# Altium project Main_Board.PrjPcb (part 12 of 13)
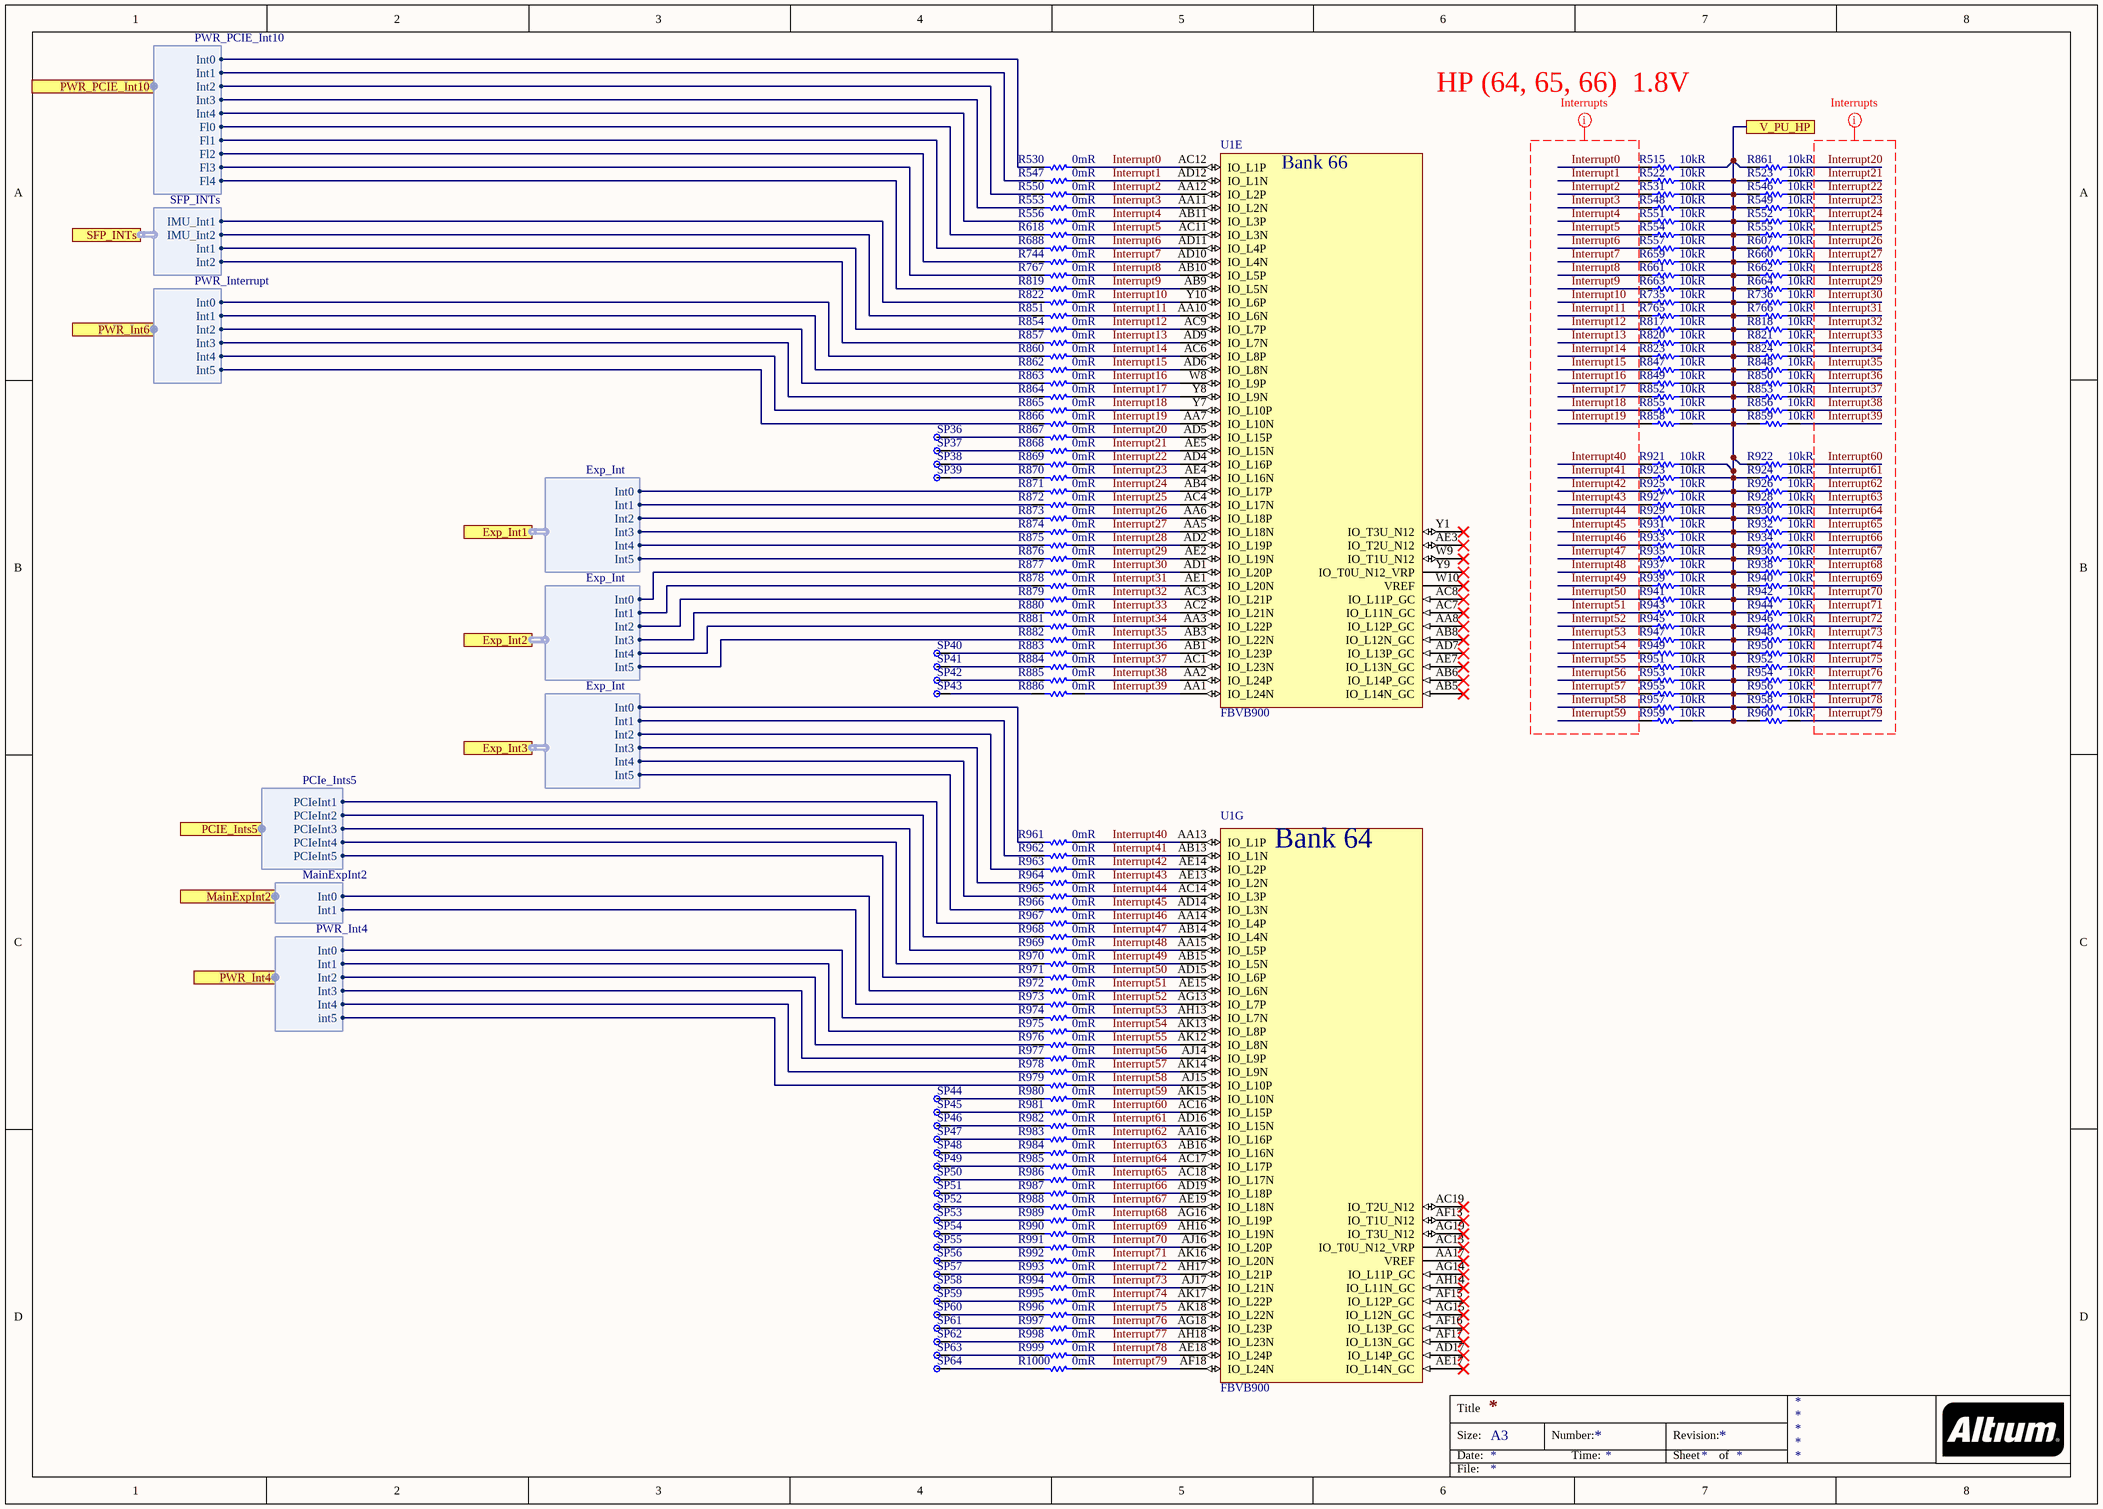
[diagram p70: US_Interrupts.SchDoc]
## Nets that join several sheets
B503_Ground: Ultrascale+_01 (13 pins), PS_Config (25 pins), LED_US_1 (9 pins), WR_Clock (5 pins), Ultrascale+_02 (U15.2 U15.10), JESD204_B_or_C (R450.2 R452.2 R454.2), HighSpeed/PCIE0 (23 pins), HighSpeed/PCIE1 (23 pins), HighSpeed/PCIE2 (23 pins), HighSpeed/PCIE3 (23 pins), HighSpeed/PCIE4 (23 pins), HighSpeed/I2C_Bridge_PCIE (C303_I2C_Bridge_PCIE.1 U3_I2C_Bridge_PCIE.9 U3_I2C_Bridge_PCIE.25), HighSpeed/SPI_bridge_PCIe (10 pins), Power4HiSpeed (50 pins), HighSpeed/Power4HighSpeed/U_Pomiar_pradu_napiecia_PCIe0 (C309_U_Pomiar_pradu_napiecia_PCIe0.1 U64_U_Pomiar_pradu_napiecia_PCIe0.7), HighSpeed/Power4HighSpeed/U_Pomiar_pradu_napiecia_PCIe1 (C309_U_Pomiar_pradu_napiecia_PCIe1.1 U64_U_Pomiar_pradu_napiecia_PCIe1.7), HighSpeed/Power4HighSpeed/U_Pomiar_pradu_napiecia_PCIe2 (C309_U_Pomiar_pradu_napiecia_PCIe2.1 U64_U_Pomiar_pradu_napiecia_PCIe2.7), HighSpeed/Power4HighSpeed/U_Pomiar_pradu_napiecia_PCIe3 (C309_U_Pomiar_pradu_napiecia_PCIe3.1 U64_U_Pomiar_pradu_napiecia_PCIe3.7), HighSpeed/Power4HighSpeed/U_Pomiar_pradu_napiecia_PCIe4 (C309_U_Pomiar_pradu_napiecia_PCIe4.1 U64_U_Pomiar_pradu_napiecia_PCIe4.7), Power_Distribution (13 pins), Power_Switch (85 pins), Power_Hi_Curr (21 pins), HI_Curr_ADP1850 (53 pins), Power_ADP1850_Dual (47 pins), Power_ADP1850_Dual_1 (47 pins), PowerDistribition/HiCurrent/U_Pomiar_pradu_napiecia_3 (C309_U_Pomiar_pradu_napiecia_3.1 U64_U_Pomiar_pradu_napiecia_3.7), PowerDistribition/HiCurrent/U_Pomiar_pradu_napiecia_4 (C309_U_Pomiar_pradu_napiecia_4.1 U64_U_Pomiar_pradu_napiecia_4.7), PowerDistribition/HiCurrent/U_Pomiar_pradu_napiecia_5 (C309_U_Pomiar_pradu_napiecia_5.1 U64_U_Pomiar_pradu_napiecia_5.7), PowerDistribition/HiCurrent/U_Pomiar_pradu_napiecia_6 (C309_U_Pomiar_pradu_napiecia_6.1 U64_U_Pomiar_pradu_napiecia_6.7), Pomiar_napiecia_high_curr (C310.1 U72.7), Power_Low_Curr (34 pins), Zasilanie_CLKDistribution (5 pins), PowerDistribition/Zasilanie CLK/I2C_Expander_PWR_CLK (C311_I2C_Expander_PWR_CLK.1 U35_I2C_Expander_PWR_CLK.6 U35_I2C_Expander_PWR_CLK.29), RAM_Power (136 pins), XilinxPower (10 pins), FPGA_Decoupling (28 pins), RAM (7 pins), Ground (286 pins), Power_Ethernet (20 pins), PowerDistribition/I2C_Expander_PWR_Dist (C311_I2C_Expander_PWR_Dist.1 U35_I2C_Expander_PWR_Dist.6 U35_I2C_Expander_PWR_Dist.29), PowerDistribition/U_Pomiar_pradu_napiecia_1 (C309_U_Pomiar_pradu_napiecia_1.1 U64_U_Pomiar_pradu_napiecia_1.7), PowerDistribition/U_Pomiar_pradu_napiecia_2 (C309_U_Pomiar_pradu_napiecia_2.1 U64_U_Pomiar_pradu_napiecia_2.7), Power_48_20V@3A (R764.1), TPS7A88_3V3_1V8_0V9V@2x1A (13 pins), ADP1741_3V3_0V85 (8 pins), ST1L08_5V_0V6 (7 pins), Power_LED (20 pins), Trans_LS_I2C0 (U36_Trans_LS_I2C0.1), GPIO_I2C (R242.2 R244.2 R400.2), Ext_GPIO/I2C_Bridge_GPIO (C303_I2C_Bridge_GPIO.1 U3_I2C_Bridge_GPIO.9 U3_I2C_Bridge_GPIO.25), Ext_GPIO_Bank0 (9 pins), Ext_GPIO/Ext_GPIO_Bank0/I2C_Expander_00 (C311_I2C_Expander_00.1 U35_I2C_Expander_00.6 U35_I2C_Expander_00.29), Ext_GPIO/Ext_GPIO_Bank0/I2C_Expander_01 (C311_I2C_Expander_01.1 U35_I2C_Expander_01.6 U35_I2C_Expander_01.29), Ext_GPIO/Ext_GPIO_Bank0/I2C_Expander_02 (C311_I2C_Expander_02.1 U35_I2C_Expander_02.6 U35_I2C_Expander_02.29), Ext_GPIO_Bank1 (9 pins), Ext_GPIO/Ext_GPIO_Bank1/I2C_Expander_10 (C311_I2C_Expander_10.1 U35_I2C_Expander_10.6 U35_I2C_Expander_10.29), Ext_GPIO/Ext_GPIO_Bank1/I2C_Expander_11 (C311_I2C_Expander_11.1 U35_I2C_Expander_11.6 U35_I2C_Expander_11.29), Ext_GPIO/Ext_GPIO_Bank1/I2C_Expander_12 (C311_I2C_Expander_12.1 U35_I2C_Expander_12.6 U35_I2C_Expander_12.29), SFP_Group (6 pins), SFP (12 pins), SFP1 (12 pins), SFP2 (12 pins), SFP3 (12 pins), SFP_Group+IMU/I2C_Bridge_SFP (C303_I2C_Bridge_SFP.1 U3_I2C_Bridge_SFP.9 U3_I2C_Bridge_SFP.25), IMU (7 pins), SFP_Group+IMU/I2C_Expander_SFP (C311_I2C_Expander_SFP.1 U35_I2C_Expander_SFP.6 U35_I2C_Expander_SFP.29), Trans_PS_I2C0 (U36_Trans_PS_I2C0.1), Trans_PS_I2C1 (U36_Trans_PS_I2C1.1), SPI_bridge_Main (10 pins), Trans_LS_I2C1 (U36_Trans_LS_I2C1.1), Detektor_otwarcia (12 pins), RJ45 (49 pins), Sata (16 pins), uSD (7 pins), FTDI (11 pins), USB3 (30 pins), CAN (C585.1 U63.2 U63.8 U75.3), eMMC (30 pins), Expander_RESET (5 pins), U_Expander_RESET/I2C_Expander_Main_Rst (C311_I2C_Expander_Main_Rst.1 U35_I2C_Expander_Main_Rst.6 U35_I2C_Expander_Main_Rst.29)
0.85V@40A_INA: HI_Curr_ADP1850 (26 pins), Pomiar_napiecia_high_curr (R617.1 U72.10)
0V9@1A_REG3: XilinxPower (6 pins), TPS7A88_3V3_1V8_0V9V@2x1A (5 pins)
0V85@2A: XilinxPower (U1.J23 U1.L23), FPGA_Decoupling (C746.2), ADP1741_3V3_0V85 (C675.2 FB45.2)
1V0@1.5A: Power_Ethernet (C555.2 R397.2 U51.8), RJ45 (14 pins)
1V8@0.5A_ADC_filtered: XilinxPower (14 pins), FPGA_Decoupling (C749.2 C750.2 C757.1 C758.2), TPS7A88_3V3_1V8_0V9V@2x1A (6 pins)
1V8@1.5A: Power_Ethernet (C553.2 R394.2 U50.8), IMU (C561.2 U58.8), RJ45 (8 pins), USB3 (C1.2 C2.2 U45.28 U45.30)
2V5@1.5A: RAM_Power (16 pins), Power_Ethernet (C551.2 R391.2 R392.2 U49.8), RJ45 (8 pins)
3.3V_LN_1: Zasilanie_CLKDistribution (12 pins), ADP1741_3.6V_3.3V@2A (C569.2 FB33.2)
3.3V_Stable_1: Zasilanie_CLKDistribution (38 pins), PowerDistribition/Zasilanie CLK/5to3V3_1 (6 pins)
3.3V_Stable_2: Zasilanie_CLKDistribution (38 pins), PowerDistribition/Zasilanie CLK/5to3V3_2 (6 pins)
3V3_NVMe: Power_Hi_Curr (8 pins), Sata (9 pins)
3V3_RAIL: LED_US_1 (9 pins), CLK_Mux (6 pins), Ultrascale+_02 (R124.2 U15.15), JESD204_B_or_C (R449.1 R451.1 R453.1), HighSpeed/PCIE0 (F1_PCIE0.2), HighSpeed/PCIE1 (F1_PCIE1.2), HighSpeed/PCIE2 (F1_PCIE2.2), HighSpeed/PCIE3 (F1_PCIE3.2), HighSpeed/PCIE4 (F1_PCIE4.2), HighSpeed/I2C_Bridge_PCIE (19 pins), HighSpeed/SPI_bridge_PCIe (30 pins), Power4HiSpeed (10 pins), HighSpeed/Power4HighSpeed/U_Pomiar_pradu_napiecia_PCIe0 (C309_U_Pomiar_pradu_napiecia_PCIe0.2 U64_U_Pomiar_pradu_napiecia_PCIe0.6), HighSpeed/Power4HighSpeed/U_Pomiar_pradu_napiecia_PCIe1 (C309_U_Pomiar_pradu_napiecia_PCIe1.2 U64_U_Pomiar_pradu_napiecia_PCIe1.6), HighSpeed/Power4HighSpeed/U_Pomiar_pradu_napiecia_PCIe2 (C309_U_Pomiar_pradu_napiecia_PCIe2.2 U64_U_Pomiar_pradu_napiecia_PCIe2.6), HighSpeed/Power4HighSpeed/U_Pomiar_pradu_napiecia_PCIe3 (C309_U_Pomiar_pradu_napiecia_PCIe3.2 U64_U_Pomiar_pradu_napiecia_PCIe3.6), HighSpeed/Power4HighSpeed/U_Pomiar_pradu_napiecia_PCIe4 (C309_U_Pomiar_pradu_napiecia_PCIe4.2 U64_U_Pomiar_pradu_napiecia_PCIe4.6), Power_Distribution (7 pins), Power_Switch (5 pins), Power_Hi_Curr (18 pins), Power_ADP1850_Dual (R287.2), PowerDistribition/HiCurrent/U_Pomiar_pradu_napiecia_3 (5 pins), PowerDistribition/HiCurrent/U_Pomiar_pradu_napiecia_4 (C309_U_Pomiar_pradu_napiecia_4.2 U64_U_Pomiar_pradu_napiecia_4.6), PowerDistribition/HiCurrent/U_Pomiar_pradu_napiecia_5 (C309_U_Pomiar_pradu_napiecia_5.2 U64_U_Pomiar_pradu_napiecia_5.6), PowerDistribition/HiCurrent/U_Pomiar_pradu_napiecia_6 (C309_U_Pomiar_pradu_napiecia_6.2 U64_U_Pomiar_pradu_napiecia_6.6), Pomiar_napiecia_high_curr (C310.2 U72.6), Power_Low_Curr (C623.2 U19.13 U19.16 U67.1), Zasilanie_CLKDistribution (R738.1 R740.1 R742.1), PowerDistribition/Zasilanie CLK/I2C_Expander_PWR_CLK (C311_I2C_Expander_PWR_CLK.2 U35_I2C_Expander_PWR_CLK.5), Power_Ethernet (14 pins), PowerDistribition/I2C_Expander_PWR_Dist (C311_I2C_Expander_PWR_Dist.2 U35_I2C_Expander_PWR_Dist.5), PowerDistribition/U_Pomiar_pradu_napiecia_1 (C309_U_Pomiar_pradu_napiecia_1.2 U64_U_Pomiar_pradu_napiecia_1.6), PowerDistribition/U_Pomiar_pradu_napiecia_2 (C309_U_Pomiar_pradu_napiecia_2.2 U64_U_Pomiar_pradu_napiecia_2.6), TPS7A88_3V3_1V8_0V9V@2x1A (7 pins), ADP1741_3V3_0V85 (7 pins), ST1L08_5V_0V6 (C721.2 R691.1 U73.2), Power_LED (18 pins), Trans_LS_I2C0 (R1122_Trans_LS_I2C0.1), GPIO_I2C (9 pins), Ext_GPIO/I2C_Bridge_GPIO (19 pins), Ext_GPIO_Bank0 (9 pins), Ext_GPIO/Ext_GPIO_Bank0/I2C_Expander_00 (C311_I2C_Expander_00.2 U35_I2C_Expander_00.5), Ext_GPIO/Ext_GPIO_Bank0/I2C_Expander_01 (C311_I2C_Expander_01.2 U35_I2C_Expander_01.5), Ext_GPIO/Ext_GPIO_Bank0/I2C_Expander_02 (C311_I2C_Expander_02.2 U35_I2C_Expander_02.5), Ext_GPIO_Bank1 (9 pins), Ext_GPIO/Ext_GPIO_Bank1/I2C_Expander_10 (C311_I2C_Expander_10.2 U35_I2C_Expander_10.5), Ext_GPIO/Ext_GPIO_Bank1/I2C_Expander_11 (C311_I2C_Expander_11.2 U35_I2C_Expander_11.5), Ext_GPIO/Ext_GPIO_Bank1/I2C_Expander_12 (C311_I2C_Expander_12.2 U35_I2C_Expander_12.5), SFP_Group (6 pins), SFP (8 pins), SFP1 (8 pins), SFP2 (8 pins), SFP3 (8 pins), SFP_Group+IMU/I2C_Bridge_SFP (19 pins), IMU (C562.2 R429.2 R600.2 U58.5), SFP_Group+IMU/I2C_Expander_SFP (C311_I2C_Expander_SFP.2 U35_I2C_Expander_SFP.5), Trans_PS_I2C0 (R1122_Trans_PS_I2C0.1 U36_Trans_PS_I2C0.2), Trans_PS_I2C1 (R1122_Trans_PS_I2C1.1), SPI_bridge_Main (30 pins), Trans_LS_I2C1 (R1122_Trans_LS_I2C1.1), uSD (C545.2 C546.2 J28.4 U47.A4), FTDI (8 pins), USB3 (7 pins), CAN (C585.2 U63.3), Expander_RESET (16 pins), U_Expander_RESET/I2C_Expander_Main_Rst (C311_I2C_Expander_Main_Rst.2 U35_I2C_Expander_Main_Rst.5)
5V_LN: DAC (R608.1 U30.1 U30.5 X2.14), Zasilanie_CLKDistribution (U12.42), LT3042_12V_5V_LNLDO (5 pins)
5V_RAIL: Power_ADP1850_Dual_1 (R315.2), PowerDistribition/HiCurrent/U_Pomiar_pradu_napiecia_6 (R448_U_Pomiar_pradu_napiecia_6.2 U64_U_Pomiar_pradu_napiecia_6.8 U64_U_Pomiar_pradu_napiecia_6.9), PowerDistribition/Zasilanie CLK/5to3V3_1 (C563_5to3V3_1.2 C564_5to3V3_1.2 U59_5to3V3_1.1 U59_5to3V3_1.2), PowerDistribition/Zasilanie CLK/5to3V3_2 (C563_5to3V3_2.2 C564_5to3V3_2.2 U59_5to3V3_2.1 U59_5to3V3_2.2), TPS7A88_5V_Dual_3.3V_3.3V (6 pins), ST1L08_5V_0V6 (C720.2 U73.1), Detektor_otwarcia (6 pins), USB3 (10 pins), eMMC (8 pins)
12V_LT3042: Power4HiSpeed (35 pins), Power_ADP1850_Dual_1 (R626.2), PowerDistribition/HiCurrent/U_Pomiar_pradu_napiecia_5 (R448_U_Pomiar_pradu_napiecia_5.2 U64_U_Pomiar_pradu_napiecia_5.8 U64_U_Pomiar_pradu_napiecia_5.9), Power_Low_Curr (10 pins), LT3042_12V_5V_LNLDO (FB34.1), UM78M_12_8V (C714.2 U71.1)
12V_PCIE0: Power4HiSpeed (7 pins), HighSpeed/Power4HighSpeed/U_Pomiar_pradu_napiecia_PCIe0 (R448_U_Pomiar_pradu_napiecia_PCIe0.1 U64_U_Pomiar_pradu_napiecia_PCIe0.10)
12V_PCIE0_CM: HighSpeed/PCIE0 (J1_PCIE0.2 J1_PCIE0.4), HighSpeed/Power4HighSpeed/U_Pomiar_pradu_napiecia_PCIe0 (R448_U_Pomiar_pradu_napiecia_PCIe0.2 U64_U_Pomiar_pradu_napiecia_PCIe0.8 U64_U_Pomiar_pradu_napiecia_PCIe0.9)
12V_PCIE1: Power4HiSpeed (7 pins), HighSpeed/Power4HighSpeed/U_Pomiar_pradu_napiecia_PCIe1 (R448_U_Pomiar_pradu_napiecia_PCIe1.1 U64_U_Pomiar_pradu_napiecia_PCIe1.10)
12V_PCIE1_CM: HighSpeed/PCIE1 (J1_PCIE1.2 J1_PCIE1.4), HighSpeed/Power4HighSpeed/U_Pomiar_pradu_napiecia_PCIe1 (R448_U_Pomiar_pradu_napiecia_PCIe1.2 U64_U_Pomiar_pradu_napiecia_PCIe1.8 U64_U_Pomiar_pradu_napiecia_PCIe1.9)
12V_PCIE2: Power4HiSpeed (7 pins), HighSpeed/Power4HighSpeed/U_Pomiar_pradu_napiecia_PCIe2 (R448_U_Pomiar_pradu_napiecia_PCIe2.1 U64_U_Pomiar_pradu_napiecia_PCIe2.10)
12V_PCIE2_CM: HighSpeed/PCIE2 (J1_PCIE2.2 J1_PCIE2.4), HighSpeed/Power4HighSpeed/U_Pomiar_pradu_napiecia_PCIe2 (R448_U_Pomiar_pradu_napiecia_PCIe2.2 U64_U_Pomiar_pradu_napiecia_PCIe2.8 U64_U_Pomiar_pradu_napiecia_PCIe2.9)
12V_PCIE3: Power4HiSpeed (7 pins), HighSpeed/Power4HighSpeed/U_Pomiar_pradu_napiecia_PCIe3 (R448_U_Pomiar_pradu_napiecia_PCIe3.1 U64_U_Pomiar_pradu_napiecia_PCIe3.10)
12V_PCIE3_CM: HighSpeed/PCIE3 (J1_PCIE3.2 J1_PCIE3.4), HighSpeed/Power4HighSpeed/U_Pomiar_pradu_napiecia_PCIe3 (R448_U_Pomiar_pradu_napiecia_PCIe3.2 U64_U_Pomiar_pradu_napiecia_PCIe3.8 U64_U_Pomiar_pradu_napiecia_PCIe3.9)
12V_PCIE4: Power4HiSpeed (7 pins), HighSpeed/Power4HighSpeed/U_Pomiar_pradu_napiecia_PCIe4 (R448_U_Pomiar_pradu_napiecia_PCIe4.1 U64_U_Pomiar_pradu_napiecia_PCIe4.10)
12V_PCIE4_CM: HighSpeed/PCIE4 (J1_PCIE4.2 J1_PCIE4.4), HighSpeed/Power4HighSpeed/U_Pomiar_pradu_napiecia_PCIe4 (R448_U_Pomiar_pradu_napiecia_PCIe4.2 U64_U_Pomiar_pradu_napiecia_PCIe4.8 U64_U_Pomiar_pradu_napiecia_PCIe4.9)
ADP1741_3.6V: Power_Low_Curr (6 pins), ADP1741_3.6V_3.3V@2A (7 pins)
ADP1741_EN: ADP1741_3.6V_3.3V@2A (U60.4), PowerDistribition/Zasilanie CLK/I2C_Expander_PWR_CLK (U35_I2C_Expander_PWR_CLK.20)
ADP1741_PG: ADP1741_3.6V_3.3V@2A (R846#1.2 U60.5), PowerDistribition/Zasilanie CLK/I2C_Expander_PWR_CLK (U35_I2C_Expander_PWR_CLK.19), Power_LED (T43.1)
AGND: System_CLK (16 pins), DAC (18 pins), CLK_Mux (47 pins), LTC6952_1 (8 pins), LTC6952 (6 pins), Zasilanie_CLKDistribution (75 pins), ADP1741_3.6V_3.3V@2A (7 pins), PowerDistribition/Zasilanie CLK/5to3V3_1 (8 pins), PowerDistribition/Zasilanie CLK/5to3V3_2 (8 pins), LT3042_12V_5V_LNLDO (10 pins), UM78M_12_8V (C713.1 C714.1 U71.2)
B223_Rx0_N: HighSpeed/PCIE0 (J1_PCIE0.21), Bank223 (U1.W3)
B223_Rx0_P: HighSpeed/PCIE0 (J1_PCIE0.19), Bank223 (U1.W4)
B223_Rx1_N: HighSpeed/PCIE0 (J1_PCIE0.27), Bank223 (U1.V5)
B223_Rx1_P: HighSpeed/PCIE0 (J1_PCIE0.25), Bank223 (U1.V6)
B223_Rx2_N: HighSpeed/PCIE1 (J1_PCIE1.21), Bank223 (U1.T5)
B223_Rx2_P: HighSpeed/PCIE1 (J1_PCIE1.19), Bank223 (U1.T6)
B223_Rx3_N: HighSpeed/PCIE1 (J1_PCIE1.27), Bank223 (U1.R3)
B223_Rx3_P: HighSpeed/PCIE1 (J1_PCIE1.25), Bank223 (U1.R4)
B223_Tx0_to_C_N: HighSpeed/PCIE0 (J1_PCIE0.26), Bank223 (C268.1)
B223_Tx0_to_C_P: HighSpeed/PCIE0 (J1_PCIE0.24), Bank223 (C267.1)
B223_Tx1_to_C_N: HighSpeed/PCIE0 (J1_PCIE0.32), Bank223 (C270.1)
B223_Tx1_to_C_P: HighSpeed/PCIE0 (J1_PCIE0.30), Bank223 (C269.1)
B223_Tx2_to_C_N: HighSpeed/PCIE1 (J1_PCIE1.26), Bank223 (C272.1)
B223_Tx2_to_C_P: HighSpeed/PCIE1 (J1_PCIE1.24), Bank223 (C271.1)
B223_Tx3_to_C_N: HighSpeed/PCIE1 (J1_PCIE1.32), Bank223 (C275.1)
B223_Tx3_to_C_P: HighSpeed/PCIE1 (J1_PCIE1.30), Bank223 (C274.1)
B224_Rx0_N: HighSpeed/PCIE2 (J1_PCIE2.21), Bank224 (U1.P5)
B224_Rx0_P: HighSpeed/PCIE2 (J1_PCIE2.19), Bank224 (U1.P6)
B224_Rx1_N: HighSpeed/PCIE2 (J1_PCIE2.27), Bank224 (U1.M5)
B224_Rx1_P: HighSpeed/PCIE2 (J1_PCIE2.25), Bank224 (U1.M6)
B224_Rx2_N: HighSpeed/PCIE3 (J1_PCIE3.21), Bank224 (U1.L3)
B224_Rx2_P: HighSpeed/PCIE3 (J1_PCIE3.19), Bank224 (U1.L4)
B224_Rx3_N: HighSpeed/PCIE3 (J1_PCIE3.27), Bank224 (U1.K5)
B224_Rx3_P: HighSpeed/PCIE3 (J1_PCIE3.25), Bank224 (U1.K6)
B224_Tx0_to_C_N: HighSpeed/PCIE2 (J1_PCIE2.26), Bank224 (C280.1)
B224_Tx0_to_C_P: HighSpeed/PCIE2 (J1_PCIE2.24), Bank224 (C279.1)
B224_Tx1_to_C_N: HighSpeed/PCIE2 (J1_PCIE2.32), Bank224 (C282.1)
B224_Tx1_to_C_P: HighSpeed/PCIE2 (J1_PCIE2.30), Bank224 (C281.1)
B224_Tx2_to_C_N: HighSpeed/PCIE3 (J1_PCIE3.26), Bank224 (C284.1)
B224_Tx2_to_C_P: HighSpeed/PCIE3 (J1_PCIE3.24), Bank224 (C283.1)
B224_Tx3_to_C_N: HighSpeed/PCIE3 (J1_PCIE3.32), Bank224 (C287.1)
B224_Tx3_to_C_P: HighSpeed/PCIE3 (J1_PCIE3.30), Bank224 (C286.1)
B225_Rx0_N: HighSpeed/PCIE4 (J1_PCIE4.21), Bank225 (U1.H5)
B225_Rx0_P: HighSpeed/PCIE4 (J1_PCIE4.19), Bank225 (U1.H6)
B225_Rx1_N: HighSpeed/PCIE4 (J1_PCIE4.27), Bank225 (U1.G7)
B225_Rx1_P: HighSpeed/PCIE4 (J1_PCIE4.25), Bank225 (U1.G8)
B225_Tx0_to_C_N: HighSpeed/PCIE4 (J1_PCIE4.26), Bank225 (C292.1)
B225_Tx0_to_C_P: HighSpeed/PCIE4 (J1_PCIE4.24), Bank225 (C291.1)
B225_Tx1_to_C_N: HighSpeed/PCIE4 (J1_PCIE4.32), Bank225 (C294.1)
B225_Tx1_to_C_P: HighSpeed/PCIE4 (J1_PCIE4.30), Bank225 (C293.1)
B225_Tx2_to_C_N: HighSpeed/PCIE4 (J1_PCIE4.38), Bank225 (C296.1)
B225_Tx2_to_C_P: HighSpeed/PCIE4 (J1_PCIE4.36), Bank225 (C295.1)
B225_Tx3_to_C_N: HighSpeed/PCIE4 (J1_PCIE4.44), Bank225 (C299.1)
B225_Tx3_to_C_P: HighSpeed/PCIE4 (J1_PCIE4.42), Bank225 (C298.1)
Bank223_MGTREF0_N: HighSpeed/PCIE0 (J1_PCIE0.39), Bank223 (C50.1 C276.2)
Bank223_MGTREF0_P: HighSpeed/PCIE0 (J1_PCIE0.37), Bank223 (C50.2 C273.2)
Bank223_MGTREF1_N: HighSpeed/PCIE1 (J1_PCIE1.37), Bank223 (C278.2 C557.1)
Bank223_MGTREF1_P: HighSpeed/PCIE1 (J1_PCIE1.39), Bank223 (C277.2 C557.2)
Bank224_MGTREF0_N: HighSpeed/PCIE2 (J1_PCIE2.39), Bank224 (C288.2 C687.2)
Bank224_MGTREF0_P: HighSpeed/PCIE2 (J1_PCIE2.37), Bank224 (C285.2 C687.1)
Bank224_MGTREF1_N: HighSpeed/PCIE3 (J1_PCIE3.39), Bank224 (C290.2 C689.2)
Bank224_MGTREF1_P: HighSpeed/PCIE3 (J1_PCIE3.37), Bank224 (C289.2 C689.1)
Bank225_MGTREF0_N: HighSpeed/PCIE4 (J1_PCIE4.39), Bank225 (C300.2 C820.2)
Bank225_MGTREF0_P: HighSpeed/PCIE4 (J1_PCIE4.37), Bank225 (C297.2 C820.1)
Battery_PWR: Power_Distribution (P11.1), Power_Switch (R679.2 R680.2 U48.2)
CAN1_RxD: Ultrascale+_01 (R798.1), CAN (U63.1)
CAN1_TxD: Ultrascale+_01 (R799.1), CAN (U63.4)
Charge_CAP: Ext_GPIO/Ext_GPIO_Bank1/I2C_Expander_11 (U35_I2C_Expander_11.4), Detektor_otwarcia (R658.2)
CLK0_EZS_N: LTC6952 (R81.1 U12.48), Ultrascale+_02 (U1.D16)
CLK0_EZS_P: LTC6952 (R81.2 U12.47), Ultrascale+_02 (U1.C16)
CLK0_SPI.~{CS}: LTC6952 (U12.1), SPI_bridge_Main (R236_SPI_bridge_Main.1 SP25_SPI_bridge_Main.1 U26_SPI_bridge_Main.11)
CLK0_SPI.CLK: LTC6952 (U12.50), SPI_bridge_Main (U26_SPI_bridge_Main.14)
CLK0_SPI.MISO: LTC6952 (U12.51), SPI_bridge_Main (U26_SPI_bridge_Main.13)
CLK0_SPI.MOSI: LTC6952 (U12.52), SPI_bridge_Main (U26_SPI_bridge_Main.12)
CLK1_SPI.~{CS}: LTC6952_1 (U13.1), SPI_bridge_Main (R233_SPI_bridge_Main.1 SP23_SPI_bridge_Main.1 U25_SPI_bridge_Main.11)
CLK1_SPI.CLK: LTC6952_1 (U13.50), SPI_bridge_Main (U25_SPI_bridge_Main.14)
CLK1_SPI.MISO: LTC6952_1 (U13.51), SPI_bridge_Main (U25_SPI_bridge_Main.13)
CLK1_SPI.MOSI: LTC6952_1 (U13.52), SPI_bridge_Main (U25_SPI_bridge_Main.12)
CSN: Power_Switch (R17.2 U4.2), Power_48_20V@3A (11 pins)
CSU: Ultrascale+_01 (P1.2 R783.1 TP34.1), Detektor_otwarcia (R649.1)
D_05028_G0: WR_Clock (R540.1 U16.45), Ultrascale+_02 (R904.2)
D_05028_G3: WR_Clock (U16.40), Ext_GPIO/Ext_GPIO_Bank1/I2C_Expander_12 (U35_I2C_Expander_12.25)
D_05028_G4: WR_Clock (U16.41), Ext_GPIO/Ext_GPIO_Bank0/I2C_Expander_00 (U35_I2C_Expander_00.28)
D_05028_G5: WR_Clock (U16.12), Ext_GPIO/Ext_GPIO_Bank1/I2C_Expander_12 (U35_I2C_Expander_12.22)
D_05028_G6: WR_Clock (U16.13), Ext_GPIO/Ext_GPIO_Bank1/I2C_Expander_12 (U35_I2C_Expander_12.21)
D_05028_S0: WR_Clock (U16.55), Ext_GPIO/Ext_GPIO_Bank1/I2C_Expander_12 (U35_I2C_Expander_12.24)
D_05028_S1: WR_Clock (U16.56), Ext_GPIO/Ext_GPIO_Bank1/I2C_Expander_12 (U35_I2C_Expander_12.23)
DAC_SPI_CLK: DAC (U30.16), SPI_bridge_Main (U27_SPI_bridge_Main.14)
DAC_SPI_MOSI: DAC (R481.1 U30.15), SPI_bridge_Main (U27_SPI_bridge_Main.12)
eMMC_clk: Ultrascale+_01 (R112.2), eMMC (U41.M6)
eMMC_cmd: Ultrascale+_01 (R111.2), eMMC (U41.M5)
eMMC_data0: Ultrascale+_01 (R105.2), eMMC (U41.A3)
eMMC_data1: Ultrascale+_01 (R107.2), eMMC (U41.A4)
eMMC_data2: Ultrascale+_01 (R108.2), eMMC (U41.A5)
eMMC_data3: Ultrascale+_01 (R110.2), eMMC (U41.B2)
eMMC_data4: Ultrascale+_01 (R101.2), eMMC (U41.B3)
eMMC_data5: Ultrascale+_01 (R102.2), eMMC (U41.B4)
eMMC_data6: Ultrascale+_01 (R103.2), eMMC (U41.B5)
eMMC_data7: Ultrascale+_01 (R104.2), eMMC (U41.B6)
eMMC_PG1: Ext_GPIO/Ext_GPIO_Bank0/I2C_Expander_01 (U35_I2C_Expander_01.4), eMMC (R340.1 U40.5)
eMMC_PG2: Ext_GPIO/Ext_GPIO_Bank0/I2C_Expander_01 (U35_I2C_Expander_01.3), eMMC (R343.1 R345.1 U42.5)
eMMC_rst: Ultrascale+_01 (R99.1 R797.1 SP19.1), eMMC (U41.K5)
EN1: TPS7A88_5V_Dual_3.3V_3.3V (U61.20), PowerDistribition/Zasilanie CLK/I2C_Expander_PWR_CLK (U35_I2C_Expander_PWR_CLK.26)
EN1_TPS: HI_Curr_ADP1850 (R277.2 R278.2 U34.14 U34.27), TPS7A88_3V3_1V8_0V9V@2x1A (U70.20), Power_LED (R916.1)
EN2: TPS7A88_5V_Dual_3.3V_3.3V (U61.6), PowerDistribition/Zasilanie CLK/I2C_Expander_PWR_CLK (U35_I2C_Expander_PWR_CLK.27)
EN2_TPS: TPS7A88_3V3_1V8_0V9V@2x1A (R745.2 U70.6 U70.17), Power_LED (T4.1)
EN_0.85V_REG1: Power_Hi_Curr (S5.8), HI_Curr_ADP1850 (U34.1 U34.8)
En_0V85@2A: Power_ADP1850_Dual (R296.2 U37.14), ADP1741_3V3_0V85 (R435.2)
EN_3V3V_REG0: Power_Hi_Curr (S5.6), Power_ADP1850_Dual (U37.1)
EN_5V_REG0: Power_Hi_Curr (S5.7), Power_ADP1850_Dual_1 (U38.8)
EN_12@8A: Power_Hi_Curr (S5.5), Power_ADP1850_Dual_1 (U38.1)
EN_Detect: Ext_GPIO/Ext_GPIO_Bank1/I2C_Expander_12 (U35_I2C_Expander_12.3), Detektor_otwarcia (R655.1)
EN_PS_LTC6952_1: PowerDistribition/Zasilanie CLK/5to3V3_1 (U59_5to3V3_1.3), PowerDistribition/Zasilanie CLK/I2C_Expander_PWR_CLK (U35_I2C_Expander_PWR_CLK.18)
EN_PS_LTC6952_2: PowerDistribition/Zasilanie CLK/5to3V3_2 (U59_5to3V3_2.3), PowerDistribition/Zasilanie CLK/I2C_Expander_PWR_CLK (U35_I2C_Expander_PWR_CLK.22)
EN_PWR_PCIE_3: Power4HiSpeed (U22.A2), Ext_GPIO/Ext_GPIO_Bank0/I2C_Expander_02 (U35_I2C_Expander_02.24)
EN_PWR_PCIE_4: Power4HiSpeed (U23.A2), Ext_GPIO/Ext_GPIO_Bank0/I2C_Expander_00 (U35_I2C_Expander_00.19)
En_PWRSwitch_PCIE0: Power4HiSpeed (U17.A2), Ext_GPIO/Ext_GPIO_Bank1/I2C_Expander_10 (U35_I2C_Expander_10.27)
En_PWRSwitch_PCIE1: Power4HiSpeed (U20.A2), Ext_GPIO/Ext_GPIO_Bank1/I2C_Expander_11 (U35_I2C_Expander_11.19)
En_PWRSwitch_PCIE2: Power4HiSpeed (U21.A2), Ext_GPIO/Ext_GPIO_Bank1/I2C_Expander_10 (U35_I2C_Expander_10.17)
EN_SEQ_LT3504: Power_Low_Curr (U67.3), ADP1741_3V3_0V85 (R646.2 U69.5), Power_LED (T48.1)
EN_SPI_Q0_MAIN: Ext_GPIO/Ext_GPIO_Bank1/I2C_Expander_11 (U35_I2C_Expander_11.20), SPI_bridge_Main (R232_SPI_bridge_Main.1)
EN_SPI_Q1: HighSpeed/SPI_bridge_PCIe (R234_SPI_bridge_PCIe.1), Ext_GPIO/Ext_GPIO_Bank1/I2C_Expander_11 (U35_I2C_Expander_11.17)
EN_SPI_Q1_MAIN: Ext_GPIO/Ext_GPIO_Bank1/I2C_Expander_11 (U35_I2C_Expander_11.22), SPI_bridge_Main (R234_SPI_bridge_Main.1)
EN_SPI_Q2: HighSpeed/SPI_bridge_PCIe (R235_SPI_bridge_PCIe.2), Ext_GPIO/Ext_GPIO_Bank1/I2C_Expander_10 (U35_I2C_Expander_10.4)
EN_SPI_Q4: HighSpeed/SPI_bridge_PCIe (R239_SPI_bridge_PCIe.1), Ext_GPIO/Ext_GPIO_Bank1/I2C_Expander_11 (U35_I2C_Expander_11.25)
EN_SPI_Q4_MAIN: Ext_GPIO/Ext_GPIO_Bank1/I2C_Expander_11 (U35_I2C_Expander_11.28), SPI_bridge_Main (R239_SPI_bridge_Main.1)
Enable_CLK: LTC6952_1 (U13.40), LTC6952 (U12.40), U_Expander_RESET/I2C_Expander_Main_Rst (U35_I2C_Expander_Main_Rst.2)
ETH_VDDIO: Ultrascale+_01 (10 pins), PS_Config (32 pins), Power_Low_Curr (6 pins), XilinxPower (11 pins), FPGA_Decoupling (C742.1 C743.2), Power_Ethernet (U68.3), Trans_PS_I2C1 (U36_Trans_PS_I2C1.2), RJ45 (24 pins), uSD (5 pins), FTDI (U53.15 U56.15 U57.15)
EXPANDER_RESET: Ultrascale+_01 (J21.2 P13.2 R811.1), LED_US_1 (R1115.2), Expander_RESET (R1003.2 T1.1)
Flag_PWRSwitch_PCIE0: Power4HiSpeed (U17.A3), US_Interrupts (R618.2)
Flag_PWRSwitch_PCIE1: Power4HiSpeed (U20.A3), US_Interrupts (R688.2)
Flag_PWRSwitch_PCIE2: Power4HiSpeed (U21.A3), US_Interrupts (R744.2)
Flag_PWRSwitch_PCIE3: Power4HiSpeed (U22.A3), US_Interrupts (R767.2)
Flag_PWRSwitch_PCIE4: Power4HiSpeed (U23.A3), US_Interrupts (R819.2)
FTDI_5V: FTDI (C559.1 C560.2 FB31.1), U_Peripherals/Debug/5V_to_3V3_for_FTDI (5 pins)
FTDI_GND: FTDI (58 pins), U_Peripherals/Debug/5V_to_3V3_for_FTDI (8 pins)
FTDI_JTAG_ON_1: Ext_GPIO/Ext_GPIO_Bank1/I2C_Expander_12 (U35_I2C_Expander_12.17), FTDI (5 pins)
FTDI_JTAG_ON_2: Ext_GPIO/Ext_GPIO_Bank1/I2C_Expander_12 (U35_I2C_Expander_12.18), FTDI (R410.1 S8.2 S9.2 U56.9)
FTDI_JTAG_ON_3: Ext_GPIO/Ext_GPIO_Bank1/I2C_Expander_12 (U35_I2C_Expander_12.19), FTDI (R635.1 S8.3 S9.3 U57.9)
FTDI_JTAG_ON_4: Ext_GPIO/Ext_GPIO_Bank1/I2C_Expander_12 (U35_I2C_Expander_12.20), FTDI (R721.1 S8.4 S9.4 U79.9)
FTDI_VccIO: FTDI (47 pins), U_Peripherals/Debug/5V_to_3V3_for_FTDI (6 pins)
GEM3_MDC: Ultrascale+_01 (R815.1), RJ45 (U39.16)
GEM3_MDIO: Ultrascale+_01 (R816.1), RJ45 (R333.2 U39.17)
GPIO_ETH_EXPANDER: Ext_GPIO/Ext_GPIO_Bank1/I2C_Expander_10 (U35_I2C_Expander_10.2), RJ45 (R715.1 U76.2)
GPIO_Exp10_Adress0: Ext_GPIO_Bank0 (R492.2 R493.1), Ext_GPIO/Ext_GPIO_Bank0/I2C_Expander_00 (U35_I2C_Expander_00.13)
GPIO_Exp10_Adress1: Ext_GPIO_Bank0 (R494.2 R495.1), Ext_GPIO/Ext_GPIO_Bank0/I2C_Expander_00 (U35_I2C_Expander_00.12)
GPIO_Exp10_Adress2: Ext_GPIO_Bank0 (R496.2 R497.1), Ext_GPIO/Ext_GPIO_Bank0/I2C_Expander_00 (U35_I2C_Expander_00.11)
GPIO_Exp10_Int0: Ext_GPIO/Ext_GPIO_Bank0/I2C_Expander_00 (U35_I2C_Expander_00.16), US_Interrupts (R871.2)
GPIO_Exp10_Int1: Ext_GPIO/Ext_GPIO_Bank0/I2C_Expander_00 (U35_I2C_Expander_00.15), US_Interrupts (R872.2)
GPIO_Exp11_Adress0: Ext_GPIO_Bank0 (R500.2 R501.1), Ext_GPIO/Ext_GPIO_Bank0/I2C_Expander_01 (U35_I2C_Expander_01.13)
GPIO_Exp11_Adress1: Ext_GPIO_Bank0 (R502.2 R503.1), Ext_GPIO/Ext_GPIO_Bank0/I2C_Expander_01 (U35_I2C_Expander_01.12)
GPIO_Exp11_Adress2: Ext_GPIO_Bank0 (R504.2 R505.1), Ext_GPIO/Ext_GPIO_Bank0/I2C_Expander_01 (U35_I2C_Expander_01.11)
GPIO_Exp11_Int0: Ext_GPIO/Ext_GPIO_Bank0/I2C_Expander_01 (U35_I2C_Expander_01.16), US_Interrupts (R873.2)
GPIO_Exp11_Int1: Ext_GPIO/Ext_GPIO_Bank0/I2C_Expander_01 (U35_I2C_Expander_01.15), US_Interrupts (R874.2)
GPIO_Exp12_Adress0: Ext_GPIO_Bank0 (R508.2 R509.1), Ext_GPIO/Ext_GPIO_Bank0/I2C_Expander_02 (U35_I2C_Expander_02.13)
GPIO_Exp12_Adress1: Ext_GPIO_Bank0 (R510.2 R511.1), Ext_GPIO/Ext_GPIO_Bank0/I2C_Expander_02 (U35_I2C_Expander_02.12)
GPIO_Exp12_Adress2: Ext_GPIO_Bank0 (R512.2 R513.1), Ext_GPIO/Ext_GPIO_Bank0/I2C_Expander_02 (U35_I2C_Expander_02.11)
GPIO_Exp12_Int0: Ext_GPIO/Ext_GPIO_Bank0/I2C_Expander_02 (U35_I2C_Expander_02.16), US_Interrupts (R875.2)
GPIO_Exp12_Int1: Ext_GPIO/Ext_GPIO_Bank0/I2C_Expander_02 (U35_I2C_Expander_02.15), US_Interrupts (R876.2)
GPIO_Exp13_Adress0: Ext_GPIO_Bank1 (R516.2 R517.1), Ext_GPIO/Ext_GPIO_Bank1/I2C_Expander_10 (U35_I2C_Expander_10.13)
GPIO_Exp13_Adress1: Ext_GPIO_Bank1 (R518.2 R519.1), Ext_GPIO/Ext_GPIO_Bank1/I2C_Expander_10 (U35_I2C_Expander_10.12)
GPIO_Exp13_Adress2: Ext_GPIO_Bank1 (R520.2 R521.1), Ext_GPIO/Ext_GPIO_Bank1/I2C_Expander_10 (U35_I2C_Expander_10.11)
GPIO_Exp13_Int0: Ext_GPIO/Ext_GPIO_Bank1/I2C_Expander_10 (U35_I2C_Expander_10.16), US_Interrupts (R877.2)
GPIO_Exp13_Int1: Ext_GPIO/Ext_GPIO_Bank1/I2C_Expander_10 (U35_I2C_Expander_10.15), US_Interrupts (R878.2)
GPIO_Exp14_Adress0: Ext_GPIO_Bank1 (R524.2 R525.1), Ext_GPIO/Ext_GPIO_Bank1/I2C_Expander_11 (U35_I2C_Expander_11.13)
GPIO_Exp14_Adress1: Ext_GPIO_Bank1 (R526.2 R527.1), Ext_GPIO/Ext_GPIO_Bank1/I2C_Expander_11 (U35_I2C_Expander_11.12)
GPIO_Exp14_Adress2: Ext_GPIO_Bank1 (R528.2 R529.1), Ext_GPIO/Ext_GPIO_Bank1/I2C_Expander_11 (U35_I2C_Expander_11.11)
GPIO_Exp14_Int0: Ext_GPIO/Ext_GPIO_Bank1/I2C_Expander_11 (U35_I2C_Expander_11.16), US_Interrupts (R879.2)
GPIO_Exp14_Int1: Ext_GPIO/Ext_GPIO_Bank1/I2C_Expander_11 (U35_I2C_Expander_11.15), US_Interrupts (R880.2)
GPIO_Exp15_Adress0: Ext_GPIO_Bank1 (R697.2 R698.1), Ext_GPIO/Ext_GPIO_Bank1/I2C_Expander_12 (U35_I2C_Expander_12.13)
GPIO_Exp15_Adress1: Ext_GPIO_Bank1 (R699.2 R700.1), Ext_GPIO/Ext_GPIO_Bank1/I2C_Expander_12 (U35_I2C_Expander_12.12)
GPIO_Exp15_Adress2: Ext_GPIO_Bank1 (R701.2 R702.1), Ext_GPIO/Ext_GPIO_Bank1/I2C_Expander_12 (U35_I2C_Expander_12.11)
GPIO_Exp15_Int0: Ext_GPIO/Ext_GPIO_Bank1/I2C_Expander_12 (U35_I2C_Expander_12.16), US_Interrupts (R881.2)
GPIO_Exp15_Int1: Ext_GPIO/Ext_GPIO_Bank1/I2C_Expander_12 (U35_I2C_Expander_12.15), US_Interrupts (R882.2)
GPIO_Exp_Reset0: Ext_GPIO/Ext_GPIO_Bank0/I2C_Expander_00 (U35_I2C_Expander_00.14), Ext_GPIO/Ext_GPIO_Bank0/I2C_Expander_01 (U35_I2C_Expander_01.14), Ext_GPIO/Ext_GPIO_Bank0/I2C_Expander_02 (U35_I2C_Expander_02.14), Expander_RESET (R746.1), U_Expander_RESET/I2C_Expander_Main_Rst (U35_I2C_Expander_Main_Rst.17)
GPIO_Exp_Reset1: Ext_GPIO/Ext_GPIO_Bank1/I2C_Expander_10 (U35_I2C_Expander_10.14), Ext_GPIO/Ext_GPIO_Bank1/I2C_Expander_11 (U35_I2C_Expander_11.14), Ext_GPIO/Ext_GPIO_Bank1/I2C_Expander_12 (U35_I2C_Expander_12.14), Expander_RESET (R747.1), U_Expander_RESET/I2C_Expander_Main_Rst (U35_I2C_Expander_Main_Rst.18)
GPIO_Exp_Reset2: Expander_RESET (R748.1), U_Expander_RESET/I2C_Expander_Main_Rst (U35_I2C_Expander_Main_Rst.19)
GPIO_I2C0.SCL: Ext_GPIO/I2C_Bridge_GPIO (R559_I2C_Bridge_GPIO.2 SP3_I2C_Bridge_GPIO.1 U3_I2C_Bridge_GPIO.2), Ext_GPIO/Ext_GPIO_Bank0/I2C_Expander_00 (U35_I2C_Expander_00.8), Ext_GPIO/Ext_GPIO_Bank0/I2C_Expander_01 (U35_I2C_Expander_01.8), Ext_GPIO/Ext_GPIO_Bank0/I2C_Expander_02 (U35_I2C_Expander_02.8)
GPIO_I2C0.SDA: Ext_GPIO/I2C_Bridge_GPIO (R560_I2C_Bridge_GPIO.2 SP2_I2C_Bridge_GPIO.1 U3_I2C_Bridge_GPIO.1), Ext_GPIO/Ext_GPIO_Bank0/I2C_Expander_00 (U35_I2C_Expander_00.9), Ext_GPIO/Ext_GPIO_Bank0/I2C_Expander_01 (U35_I2C_Expander_01.9), Ext_GPIO/Ext_GPIO_Bank0/I2C_Expander_02 (U35_I2C_Expander_02.9)
GPIO_I2C4.SCL: Ext_GPIO/I2C_Bridge_GPIO (R9_I2C_Bridge_GPIO.2 SP11_I2C_Bridge_GPIO.1 U3_I2C_Bridge_GPIO.11), Ext_GPIO/Ext_GPIO_Bank1/I2C_Expander_10 (U35_I2C_Expander_10.8), Ext_GPIO/Ext_GPIO_Bank1/I2C_Expander_11 (U35_I2C_Expander_11.8), Ext_GPIO/Ext_GPIO_Bank1/I2C_Expander_12 (U35_I2C_Expander_12.8)
GPIO_I2C4.SDA: Ext_GPIO/I2C_Bridge_GPIO (R10_I2C_Bridge_GPIO.2 SP10_I2C_Bridge_GPIO.1 U3_I2C_Bridge_GPIO.10), Ext_GPIO/Ext_GPIO_Bank1/I2C_Expander_10 (U35_I2C_Expander_10.9), Ext_GPIO/Ext_GPIO_Bank1/I2C_Expander_11 (U35_I2C_Expander_11.9), Ext_GPIO/Ext_GPIO_Bank1/I2C_Expander_12 (U35_I2C_Expander_12.9)
GPIOa_00.GPIO5: Power_Ethernet (U51.5), Power_LED (T46.1), GPIO_I2C (R827.2), Ext_GPIO/Ext_GPIO_Bank0/I2C_Expander_00 (U35_I2C_Expander_00.22)
GPIOa_00.GPIO6: Power_Ethernet (U50.5), Power_LED (T42.1), GPIO_I2C (R826.2), Ext_GPIO/Ext_GPIO_Bank0/I2C_Expander_00 (U35_I2C_Expander_00.23)
GPIOa_01.GPIO5: Ext_GPIO/Ext_GPIO_Bank0/I2C_Expander_01 (U35_I2C_Expander_01.22), USB3 (U46.A3)
GPIOa_02.GPIO0: HighSpeed/PCIE0 (J1_PCIE0.18), Ext_GPIO/Ext_GPIO_Bank0/I2C_Expander_02 (U35_I2C_Expander_02.17)
GPIOa_02.GPIO1: Ext_GPIO/Ext_GPIO_Bank0/I2C_Expander_02 (U35_I2C_Expander_02.18), SPI_bridge_Main (R237_SPI_bridge_Main.2)
GPIOa_11.GPIO1: HighSpeed/PCIE1 (J1_PCIE1.18), Ext_GPIO/Ext_GPIO_Bank1/I2C_Expander_11 (U35_I2C_Expander_11.18)
GPIOa_11.GPIO7: WR_Clock (R499.1), Ext_GPIO/Ext_GPIO_Bank1/I2C_Expander_11 (U35_I2C_Expander_11.24)
GPIOb_00.GPIO4: WR_Clock (U16.29), Ext_GPIO/Ext_GPIO_Bank0/I2C_Expander_00 (U35_I2C_Expander_00.1)
GPIOb_00.GPIO5: WR_Clock (U16.28), Ext_GPIO/Ext_GPIO_Bank0/I2C_Expander_00 (U35_I2C_Expander_00.2)
GPIOb_00.GPIO6: WR_Clock (U16.20), Ext_GPIO/Ext_GPIO_Bank0/I2C_Expander_00 (U35_I2C_Expander_00.3)
GPIOb_00.GPIO7: WR_Clock (U16.17), Ext_GPIO/Ext_GPIO_Bank0/I2C_Expander_00 (U35_I2C_Expander_00.4)
GPIOb_01.GPIO2: Ext_GPIO/Ext_GPIO_Bank0/I2C_Expander_01 (U35_I2C_Expander_01.27), SPI_bridge_Main (R235_SPI_bridge_Main.2)
GPIOb_02.GPIO0: HighSpeed/I2C_Bridge_PCIE (SP12_I2C_Bridge_PCIE.1 U3_I2C_Bridge_PCIE.24), Ext_GPIO/Ext_GPIO_Bank0/I2C_Expander_02 (U35_I2C_Expander_02.25)
GPIOb_02.GPIO2: HighSpeed/PCIE3 (J1_PCIE3.18), Ext_GPIO/Ext_GPIO_Bank0/I2C_Expander_02 (U35_I2C_Expander_02.27)
GPIOb_02.GPIO3: HighSpeed/SPI_bridge_PCIe (R237_SPI_bridge_PCIe.2), Ext_GPIO/Ext_GPIO_Bank0/I2C_Expander_02 (U35_I2C_Expander_02.28)
GPIOb_02.GPIO4: ST1L08_5V_0V6 (R691.2 U73.6), Power_LED (T44.1), Ext_GPIO/Ext_GPIO_Bank0/I2C_Expander_02 (U35_I2C_Expander_02.1)
GPIOb_02.GPIO5: HighSpeed/SPI_bridge_PCIe (R232_SPI_bridge_PCIe.1), Ext_GPIO/Ext_GPIO_Bank0/I2C_Expander_02 (U35_I2C_Expander_02.2)
GPIOb_10.GPIO6: HighSpeed/PCIE2 (J1_PCIE2.18), Ext_GPIO/Ext_GPIO_Bank1/I2C_Expander_10 (U35_I2C_Expander_10.3)
GPIOb_11.GPIO1: HighSpeed/PCIE4 (J1_PCIE4.18), Ext_GPIO/Ext_GPIO_Bank1/I2C_Expander_11 (U35_I2C_Expander_11.26)
GPIOb_12.GPIO2: WR_Clock (R540.2), Ext_GPIO/Ext_GPIO_Bank1/I2C_Expander_12 (U35_I2C_Expander_12.27)
GPIOb_12.GPIO7: Power_Low_Curr (U19.23), Power_LED (T3.1), GPIO_I2C (R825.2), Ext_GPIO/Ext_GPIO_Bank1/I2C_Expander_12 (U35_I2C_Expander_12.4)
Ground: WR_Clock (6 pins), Zasilanie_CLKDistribution (52 pins), TPS7A88_5V_Dual_3.3V_3.3V (13 pins)
HiSpeedModule_I2C0.SCL: HighSpeed/I2C_Bridge_PCIE (R225_I2C_Bridge_PCIE.2 SP7_I2C_Bridge_PCIE.1 U3_I2C_Bridge_PCIE.6), Power4HiSpeed (R185.2 R189.2 R213.2 R221.2), HighSpeed/Power4HighSpeed/U_Pomiar_pradu_napiecia_PCIe1 (U64_U_Pomiar_pradu_napiecia_PCIe1.5), HighSpeed/Power4HighSpeed/U_Pomiar_pradu_napiecia_PCIe4 (U64_U_Pomiar_pradu_napiecia_PCIe4.5)
HiSpeedModule_I2C0.SDA: HighSpeed/I2C_Bridge_PCIE (R226_I2C_Bridge_PCIE.2 SP6_I2C_Bridge_PCIE.1 U3_I2C_Bridge_PCIE.5), Power4HiSpeed (R186.2 R190.2 R215.2 R222.2), HighSpeed/Power4HighSpeed/U_Pomiar_pradu_napiecia_PCIe1 (U64_U_Pomiar_pradu_napiecia_PCIe1.4), HighSpeed/Power4HighSpeed/U_Pomiar_pradu_napiecia_PCIe4 (U64_U_Pomiar_pradu_napiecia_PCIe4.4)
HiSpeedModule_I2C1.SCL: HighSpeed/PCIE0 (J1_PCIE0.15), HighSpeed/I2C_Bridge_PCIE (R227_I2C_Bridge_PCIE.2 SP5_I2C_Bridge_PCIE.1 U3_I2C_Bridge_PCIE.4)
HiSpeedModule_I2C1.SDA: HighSpeed/PCIE0 (J1_PCIE0.13), HighSpeed/I2C_Bridge_PCIE (R558_I2C_Bridge_PCIE.2 SP4_I2C_Bridge_PCIE.1 U3_I2C_Bridge_PCIE.3)
HiSpeedModule_I2C2.SCL: HighSpeed/PCIE1 (J1_PCIE1.15), HighSpeed/I2C_Bridge_PCIE (R223_I2C_Bridge_PCIE.2 SP9_I2C_Bridge_PCIE.1 U3_I2C_Bridge_PCIE.8)
HiSpeedModule_I2C2.SDA: HighSpeed/PCIE1 (J1_PCIE1.13), HighSpeed/I2C_Bridge_PCIE (R224_I2C_Bridge_PCIE.2 SP8_I2C_Bridge_PCIE.1 U3_I2C_Bridge_PCIE.7)
HiSpeedModule_I2C3.SCL: HighSpeed/PCIE2 (J1_PCIE2.15), HighSpeed/I2C_Bridge_PCIE (R9_I2C_Bridge_PCIE.2 SP11_I2C_Bridge_PCIE.1 U3_I2C_Bridge_PCIE.11)
HiSpeedModule_I2C3.SDA: HighSpeed/PCIE2 (J1_PCIE2.13), HighSpeed/I2C_Bridge_PCIE (R10_I2C_Bridge_PCIE.2 SP10_I2C_Bridge_PCIE.1 U3_I2C_Bridge_PCIE.10)
HiSpeedModule_I2C4.SCL: HighSpeed/PCIE3 (J1_PCIE3.15), HighSpeed/I2C_Bridge_PCIE (R559_I2C_Bridge_PCIE.2 SP3_I2C_Bridge_PCIE.1 U3_I2C_Bridge_PCIE.2)
HiSpeedModule_I2C4.SDA: HighSpeed/PCIE3 (J1_PCIE3.13), HighSpeed/I2C_Bridge_PCIE (R560_I2C_Bridge_PCIE.2 SP2_I2C_Bridge_PCIE.1 U3_I2C_Bridge_PCIE.1)
HiSpeedModule_I2C5.SCL: HighSpeed/PCIE4 (J1_PCIE4.15), HighSpeed/I2C_Bridge_PCIE (R7_I2C_Bridge_PCIE.2 SP14_I2C_Bridge_PCIE.1 U3_I2C_Bridge_PCIE.13)
HiSpeedModule_I2C5.SDA: HighSpeed/PCIE4 (J1_PCIE4.13), HighSpeed/I2C_Bridge_PCIE (R8_I2C_Bridge_PCIE.2 SP13_I2C_Bridge_PCIE.1 U3_I2C_Bridge_PCIE.12)
HiSpeedModule_I2C6.SCL: HighSpeed/I2C_Bridge_PCIE (R5_I2C_Bridge_PCIE.2 SP16_I2C_Bridge_PCIE.1 U3_I2C_Bridge_PCIE.15), Power4HiSpeed (R176.2 R180.2 R194.2 R198.2), HighSpeed/Power4HighSpeed/U_Pomiar_pradu_napiecia_PCIe0 (U64_U_Pomiar_pradu_napiecia_PCIe0.5), HighSpeed/Power4HighSpeed/U_Pomiar_pradu_napiecia_PCIe2 (U64_U_Pomiar_pradu_napiecia_PCIe2.5)
HiSpeedModule_I2C6.SDA: HighSpeed/I2C_Bridge_PCIE (R6_I2C_Bridge_PCIE.2 SP15_I2C_Bridge_PCIE.1 U3_I2C_Bridge_PCIE.14), Power4HiSpeed (R177.2 R181.2 R195.2 R199.2), HighSpeed/Power4HighSpeed/U_Pomiar_pradu_napiecia_PCIe0 (U64_U_Pomiar_pradu_napiecia_PCIe0.4), HighSpeed/Power4HighSpeed/U_Pomiar_pradu_napiecia_PCIe2 (U64_U_Pomiar_pradu_napiecia_PCIe2.4)
HiSpeedModule_I2C7.SCL: HighSpeed/I2C_Bridge_PCIE (R3_I2C_Bridge_PCIE.2 SP18_I2C_Bridge_PCIE.1 U3_I2C_Bridge_PCIE.17), Power4HiSpeed (R203.2 R207.2), HighSpeed/Power4HighSpeed/U_Pomiar_pradu_napiecia_PCIe3 (U64_U_Pomiar_pradu_napiecia_PCIe3.5)
HiSpeedModule_I2C7.SDA: HighSpeed/I2C_Bridge_PCIE (R4_I2C_Bridge_PCIE.2 SP17_I2C_Bridge_PCIE.1 U3_I2C_Bridge_PCIE.16), Power4HiSpeed (R204.2 R208.2), HighSpeed/Power4HighSpeed/U_Pomiar_pradu_napiecia_PCIe3 (U64_U_Pomiar_pradu_napiecia_PCIe3.4)
HiSpeedModule_SPI0.~{CS}: HighSpeed/PCIE0 (J1_PCIE0.51), HighSpeed/SPI_bridge_PCIe (R231_SPI_bridge_PCIe.1 SP21_SPI_bridge_PCIe.1 U24_SPI_bridge_PCIe.11)
HiSpeedModule_SPI0.CLK: HighSpeed/PCIE0 (J1_PCIE0.45), HighSpeed/SPI_bridge_PCIe (U24_SPI_bridge_PCIe.14)
HiSpeedModule_SPI0.MISO: HighSpeed/PCIE0 (J1_PCIE0.49), HighSpeed/SPI_bridge_PCIe (U24_SPI_bridge_PCIe.13)
HiSpeedModule_SPI0.MOSI: HighSpeed/PCIE0 (J1_PCIE0.47), HighSpeed/SPI_bridge_PCIe (U24_SPI_bridge_PCIe.12)
HiSpeedModule_SPI1.~{CS}: HighSpeed/PCIE1 (J1_PCIE1.51), HighSpeed/SPI_bridge_PCIe (R233_SPI_bridge_PCIe.1 SP23_SPI_bridge_PCIe.1 U25_SPI_bridge_PCIe.11)
HiSpeedModule_SPI1.CLK: HighSpeed/PCIE1 (J1_PCIE1.45), HighSpeed/SPI_bridge_PCIe (U25_SPI_bridge_PCIe.14)
HiSpeedModule_SPI1.MISO: HighSpeed/PCIE1 (J1_PCIE1.49), HighSpeed/SPI_bridge_PCIe (U25_SPI_bridge_PCIe.13)
HiSpeedModule_SPI1.MOSI: HighSpeed/PCIE1 (J1_PCIE1.47), HighSpeed/SPI_bridge_PCIe (U25_SPI_bridge_PCIe.12)
HiSpeedModule_SPI2.~{CS}: HighSpeed/PCIE2 (J1_PCIE2.51), HighSpeed/SPI_bridge_PCIe (R236_SPI_bridge_PCIe.1 SP25_SPI_bridge_PCIe.1 U26_SPI_bridge_PCIe.11)
HiSpeedModule_SPI2.CLK: HighSpeed/PCIE2 (J1_PCIE2.45), HighSpeed/SPI_bridge_PCIe (U26_SPI_bridge_PCIe.14)
HiSpeedModule_SPI2.MISO: HighSpeed/PCIE2 (J1_PCIE2.49), HighSpeed/SPI_bridge_PCIe (U26_SPI_bridge_PCIe.13)
HiSpeedModule_SPI2.MOSI: HighSpeed/PCIE2 (J1_PCIE2.47), HighSpeed/SPI_bridge_PCIe (U26_SPI_bridge_PCIe.12)
HiSpeedModule_SPI3.~{CS}: HighSpeed/PCIE3 (J1_PCIE3.51), HighSpeed/SPI_bridge_PCIe (R238_SPI_bridge_PCIe.1 SP27_SPI_bridge_PCIe.1 U27_SPI_bridge_PCIe.11)
HiSpeedModule_SPI3.CLK: HighSpeed/PCIE3 (J1_PCIE3.45), HighSpeed/SPI_bridge_PCIe (U27_SPI_bridge_PCIe.14)
HiSpeedModule_SPI3.MISO: HighSpeed/PCIE3 (J1_PCIE3.49), HighSpeed/SPI_bridge_PCIe (U27_SPI_bridge_PCIe.13)
HiSpeedModule_SPI3.MOSI: HighSpeed/PCIE3 (J1_PCIE3.47), HighSpeed/SPI_bridge_PCIe (U27_SPI_bridge_PCIe.12)
HiSpeedModule_SPI4.~{CS}: HighSpeed/PCIE4 (J1_PCIE4.51), HighSpeed/SPI_bridge_PCIe (R240_SPI_bridge_PCIe.1 SP29_SPI_bridge_PCIe.1 U28_SPI_bridge_PCIe.11)
HiSpeedModule_SPI4.CLK: HighSpeed/PCIE4 (J1_PCIE4.45), HighSpeed/SPI_bridge_PCIe (U28_SPI_bridge_PCIe.14)
HiSpeedModule_SPI4.MISO: HighSpeed/PCIE4 (J1_PCIE4.49), HighSpeed/SPI_bridge_PCIe (U28_SPI_bridge_PCIe.13)
HiSpeedModule_SPI4.MOSI: HighSpeed/PCIE4 (J1_PCIE4.47), HighSpeed/SPI_bridge_PCIe (U28_SPI_bridge_PCIe.12)
I2C0_PS.SCL: Ultrascale+_01 (J12.1 R85.1 R774.1), Trans_PS_I2C0 (SP34_Trans_PS_I2C0.1 U36_Trans_PS_I2C0.3)
I2C0_PS.SDA: Ultrascale+_01 (J12.2 R86.1 R775.1), Trans_PS_I2C0 (SP35_Trans_PS_I2C0.1 U36_Trans_PS_I2C0.4)
I2C0_Rail.SCL: Trans_LS_I2C0 (U36_Trans_LS_I2C0.6), SFP_Group+IMU/I2C_Bridge_SFP (U3_I2C_Bridge_SFP.19), Trans_PS_I2C0 (U36_Trans_PS_I2C0.6)
I2C0_Rail.SDA: Trans_LS_I2C0 (U36_Trans_LS_I2C0.5), SFP_Group+IMU/I2C_Bridge_SFP (U3_I2C_Bridge_SFP.20), Trans_PS_I2C0 (U36_Trans_PS_I2C0.5)
I2C1_PS.SCL: Ultrascale+_01 (J13.1 R83.1 R772.1), Trans_PS_I2C1 (SP34_Trans_PS_I2C1.1 U36_Trans_PS_I2C1.3)
I2C1_PS.SDA: Ultrascale+_01 (J13.2 R84.1 R773.1), Trans_PS_I2C1 (SP35_Trans_PS_I2C1.1 U36_Trans_PS_I2C1.4)
I2C1_Rail.SCL: GPIO_I2C (R599.1), Ext_GPIO/I2C_Bridge_GPIO (U3_I2C_Bridge_GPIO.19), Trans_PS_I2C1 (U36_Trans_PS_I2C1.6), Trans_LS_I2C1 (U36_Trans_LS_I2C1.6), U_Expander_RESET/I2C_Expander_Main_Rst (U35_I2C_Expander_Main_Rst.8)
I2C1_Rail.SDA: GPIO_I2C (R428.1), Ext_GPIO/I2C_Bridge_GPIO (U3_I2C_Bridge_GPIO.20), Trans_PS_I2C1 (U36_Trans_PS_I2C1.5), Trans_LS_I2C1 (U36_Trans_LS_I2C1.5), U_Expander_RESET/I2C_Expander_Main_Rst (U35_I2C_Expander_Main_Rst.9)
I2C_LS.SCL: Ultrascale+_02 (R363.2 U1.AG1), Trans_LS_I2C0 (SP34_Trans_LS_I2C0.1 U36_Trans_LS_I2C0.3), Trans_LS_I2C1 (SP34_Trans_LS_I2C1.1 U36_Trans_LS_I2C1.3)
I2C_LS.SDA: Ultrascale+_02 (R364.2 U1.AF3), Trans_LS_I2C0 (SP35_Trans_LS_I2C0.1 U36_Trans_LS_I2C0.4), Trans_LS_I2C1 (SP35_Trans_LS_I2C1.1 U36_Trans_LS_I2C1.4)
I2C_SCL_SFP0: SFP (J32.5), SFP_Group+IMU/I2C_Bridge_SFP (R225_I2C_Bridge_SFP.2 SP7_I2C_Bridge_SFP.1 U3_I2C_Bridge_SFP.6)
I2C_SCL_SFP1: SFP1 (J33.5), SFP_Group+IMU/I2C_Bridge_SFP (R559_I2C_Bridge_SFP.2 SP3_I2C_Bridge_SFP.1 U3_I2C_Bridge_SFP.2)
I2C_SCL_SFP2: SFP2 (J34.5), SFP_Group+IMU/I2C_Bridge_SFP (R223_I2C_Bridge_SFP.2 SP9_I2C_Bridge_SFP.1 U3_I2C_Bridge_SFP.8)
I2C_SCL_SFP3: SFP3 (J35.5), SFP_Group+IMU/I2C_Bridge_SFP (R227_I2C_Bridge_SFP.2 SP5_I2C_Bridge_SFP.1 U3_I2C_Bridge_SFP.4)
I2C_SDA_SFP0: SFP (J32.4), SFP_Group+IMU/I2C_Bridge_SFP (R226_I2C_Bridge_SFP.2 SP6_I2C_Bridge_SFP.1 U3_I2C_Bridge_SFP.5)
I2C_SDA_SFP1: SFP1 (J33.4), SFP_Group+IMU/I2C_Bridge_SFP (R560_I2C_Bridge_SFP.2 SP2_I2C_Bridge_SFP.1 U3_I2C_Bridge_SFP.1)
I2C_SDA_SFP2: SFP2 (J34.4), SFP_Group+IMU/I2C_Bridge_SFP (R224_I2C_Bridge_SFP.2 SP8_I2C_Bridge_SFP.1 U3_I2C_Bridge_SFP.7)
I2C_SDA_SFP3: SFP3 (J35.4), SFP_Group+IMU/I2C_Bridge_SFP (R558_I2C_Bridge_SFP.2 SP4_I2C_Bridge_SFP.1 U3_I2C_Bridge_SFP.3)
IMU_INT1: IMU (U58.4), US_Interrupts (R822.2)
IMU_INT2: IMU (U58.9), US_Interrupts (R851.2)
INTA_EXP_MAIN: U_Expander_RESET/I2C_Expander_Main_Rst (U35_I2C_Expander_Main_Rst.16), US_Interrupts (R972.2)
INTB_EXP_MAIN: U_Expander_RESET/I2C_Expander_Main_Rst (U35_I2C_Expander_Main_Rst.15), US_Interrupts (R973.2)
JTAG_CLK: RJ45 (U39.20), FTDI (R1042.1)
JTAG_TDI: RJ45 (R336.2 U39.23), FTDI (R1040.1)
JTAG_TDO: RJ45 (R337.2 U39.21), FTDI (R1043.1)
JTAG_TMS: RJ45 (R338.2 U39.22), FTDI (R1041.1)
LTC6952_0_MATCH_Out0_N: LTC6952 (C315.1 R1054.1), HighSpeed/PCIE0 (J1_PCIE0.7)
LTC6952_0_MATCH_Out0_P: LTC6952 (C315.2 R539.1), HighSpeed/PCIE0 (J1_PCIE0.5)
LTC6952_0_MATCH_Out1_N: LTC6952 (C317.1 R1056.1), HighSpeed/PCIE3 (J1_PCIE3.7)
LTC6952_0_MATCH_Out1_P: LTC6952 (C317.2 R1055.1), HighSpeed/PCIE3 (J1_PCIE3.5)
LTC6952_0_MATCH_Out3_N: LTC6952_1 (R535.1 U13.48), LTC6952 (R1074.1)
LTC6952_0_MATCH_Out3_P: LTC6952_1 (R535.2 U13.47), LTC6952 (R1073.1)
LTC6952_0_MATCH_Out4_N: LTC6952_1 (R534.2 U13.37), LTC6952 (R1072.2)
LTC6952_0_MATCH_Out4_P: LTC6952_1 (R534.1 U13.38), LTC6952 (R1071.2)
LTC6952_0_MATCH_Out6_N: LTC6952 (C602.2 R1068.1), Sata (J27.53)
LTC6952_0_MATCH_Out6_P: LTC6952 (C602.1 R1067.1), Sata (J27.55)
LTC6952_0_MATCH_Out7_N: LTC6952 (C608.1 U12.12), GTR (C526.2)
LTC6952_0_MATCH_Out7_P: LTC6952 (C608.2 U12.13), GTR (C525.2)
LTC6952_0_MATCH_Out8_N: LTC6952 (C682.1 U12.9), GTR (C528.2)
LTC6952_0_MATCH_Out8_P: LTC6952 (C682.2 U12.10), GTR (C527.2)
LTC6952_0_MATCH_Out9_N: LTC6952 (C684.1 U12.6), GTR (C530.2)
LTC6952_0_MATCH_Out9_P: LTC6952 (C684.2 U12.7), GTR (C529.2)
LTC6952_1_CP_Out: System_CLK (C46.2 R77.2 TP19.1 X1.2), LTC6952 (U12.43)
LTC6952_1_MATCH_Out0_N: LTC6952_1 (C41.2 C119#1.2), bank226 (U1.D9)
LTC6952_1_MATCH_Out0_P: LTC6952_1 (C41.1 C118#1.2), bank226 (U1.D10)
LTC6952_1_MATCH_Out1_N: LTC6952_1 (C799.2 R1092.1), Ultrascale+_02 (U1.AH2)
LTC6952_1_MATCH_Out1_P: LTC6952_1 (C799.1 R1091.1), Ultrascale+_02 (U1.AH3)
LTC6952_1_MATCH_Out2_N: LTC6952_1 (C802.2 R1094.1), HighSpeed/PCIE2 (J1_PCIE2.7)
LTC6952_1_MATCH_Out2_P: LTC6952_1 (C802.1 R1093.1), HighSpeed/PCIE2 (J1_PCIE2.5)
LTC6952_1_MATCH_Out7_N: LTC6952_1 (C814.2 R1106.1), HighSpeed/PCIE1 (J1_PCIE1.7)
LTC6952_1_MATCH_Out7_P: LTC6952_1 (C814.1 R1105.1), HighSpeed/PCIE1 (J1_PCIE1.5)
LTC6952_1_MATCH_Out8_N: WR_Clock (C690.2 R1084.1), LTC6952_1 (U13.9)
LTC6952_1_MATCH_Out8_P: WR_Clock (C690.1 R1083.1), LTC6952_1 (U13.10)
LTC6952_1_MATCH_Out9_N: LTC6952_1 (C818.2 R1110.1), HighSpeed/PCIE4 (J1_PCIE4.7)
LTC6952_1_MATCH_Out9_P: LTC6952_1 (C818.1 R1109.1), HighSpeed/PCIE4 (J1_PCIE4.5)
LTC6952_1_Temp: LTC6952 (U12.49), Ultrascale+_02 (R395.2)
LTC6952_1_VCO_N: System_CLK (C334.1 R532.2), LTC6952 (R80.2 U12.37)
LTC6952_1_VCO_P: System_CLK (R533.2), LTC6952 (R80.1 U12.38)
LTC6952_2_Temp: LTC6952_1 (U13.49), Ultrascale+_02 (R398.2)
MainExpReset: Expander_RESET (R1002.1 T1.3), U_Expander_RESET/I2C_Expander_Main_Rst (U35_I2C_Expander_Main_Rst.14)
MIO_GPIO_0_12: Ultrascale+_01 (J15.2 R780.1), LED_US_1 (R1095.2)
MIO_GPIO_0_23: Ultrascale+_01 (J16.2 R98.1 R781.1), LED_US_1 (R1099.2)
MIO_GPIO_1_38: Ultrascale+_01 (J17.2 R796.1 TP36.1), LED_US_1 (R1107.2)
MIO_GPIO_2_66: Ultrascale+_01 (J19.2 R805.1), LED_US_1 (R1111.2)
MIO_GPIO_2_70: Ultrascale+_01 (J20.2 R809.1), LED_US_1 (R1113.2)
MIO_GPIO_2_73: Ultrascale+_01 (J22.2 R812.1), LED_US_1 (R1117.2)
MIO_GPIO_2_74: Ultrascale+_01 (J23.2 R813.1), LED_US_1 (R1119.2), Trans_PS_I2C1 (U36_Trans_PS_I2C1.8)
MIO_GPIO_2_75: Ultrascale+_01 (J24.2 R814.1), LED_US_1 (R1121.2), Trans_PS_I2C0 (U36_Trans_PS_I2C0.8)
NetC713_2: System_CLK (X1.14), UM78M_12_8V (C713.2 U71.3)
NetJ1_PCIE0_20: Ultrascale+_02 (R507.2), HighSpeed/PCIE0 (J1_PCIE0.20)
NetJ1_PCIE0_43: HighSpeed/PCIE0 (J1_PCIE0.43), US_Interrupts (R967.2)
NetJ1_PCIE1_20: Ultrascale+_02 (R514.2), HighSpeed/PCIE1 (J1_PCIE1.20)
NetJ1_PCIE1_43: HighSpeed/PCIE1 (J1_PCIE1.43), US_Interrupts (R968.2)
NetJ1_PCIE2_20: Ultrascale+_02 (R901.2), HighSpeed/PCIE2 (J1_PCIE2.20)
NetJ1_PCIE2_43: HighSpeed/PCIE2 (J1_PCIE2.43), US_Interrupts (R969.2)
NetJ1_PCIE3_20: Ultrascale+_02 (R902.2), HighSpeed/PCIE3 (J1_PCIE3.20)
NetJ1_PCIE3_43: HighSpeed/PCIE3 (J1_PCIE3.43), US_Interrupts (R970.2)
NetJ1_PCIE4_20: Ultrascale+_02 (R903.2), HighSpeed/PCIE4 (J1_PCIE4.20)
NetJ1_PCIE4_43: HighSpeed/PCIE4 (J1_PCIE4.43), US_Interrupts (R971.2)
NetR14_1: Power_Hi_Curr (R14.1 R16.1 R22.1 R24.1), Pomiar_napiecia_high_curr (U72.2)
NetR132_1: WR_Clock (R132.1), SPI_bridge_Main (U28_SPI_bridge_Main.14)
NetR133_1: WR_Clock (R133.1), SPI_bridge_Main (U28_SPI_bridge_Main.13)
NetR134_1: WR_Clock (R134.1), SPI_bridge_Main (U28_SPI_bridge_Main.12)
NetR174_1: Power4HiSpeed (R174.1 R175.1 R176.1 R177.1), HighSpeed/Power4HighSpeed/U_Pomiar_pradu_napiecia_PCIe0 (U64_U_Pomiar_pradu_napiecia_PCIe0.2)
NetR178_1: Power4HiSpeed (R178.1 R179.1 R180.1 R181.1), HighSpeed/Power4HighSpeed/U_Pomiar_pradu_napiecia_PCIe0 (U64_U_Pomiar_pradu_napiecia_PCIe0.1)
NetR183_1: Power4HiSpeed (R183.1 R184.1 R185.1 R186.1), HighSpeed/Power4HighSpeed/U_Pomiar_pradu_napiecia_PCIe1 (U64_U_Pomiar_pradu_napiecia_PCIe1.2)
NetR187_1: Power4HiSpeed (R187.1 R188.1 R189.1 R190.1), HighSpeed/Power4HighSpeed/U_Pomiar_pradu_napiecia_PCIe1 (U64_U_Pomiar_pradu_napiecia_PCIe1.1)
NetR192_1: Power4HiSpeed (R192.1 R193.1 R194.1 R195.1), HighSpeed/Power4HighSpeed/U_Pomiar_pradu_napiecia_PCIe2 (U64_U_Pomiar_pradu_napiecia_PCIe2.2)
NetR196_1: Power4HiSpeed (R196.1 R197.1 R198.1 R199.1), HighSpeed/Power4HighSpeed/U_Pomiar_pradu_napiecia_PCIe2 (U64_U_Pomiar_pradu_napiecia_PCIe2.1)
NetR201_1: Power4HiSpeed (R201.1 R202.1 R203.1 R204.1), HighSpeed/Power4HighSpeed/U_Pomiar_pradu_napiecia_PCIe3 (U64_U_Pomiar_pradu_napiecia_PCIe3.2)
NetR205_1: Power4HiSpeed (R205.1 R206.1 R207.1 R208.1), HighSpeed/Power4HighSpeed/U_Pomiar_pradu_napiecia_PCIe3 (U64_U_Pomiar_pradu_napiecia_PCIe3.1)
NetR210_1: Power4HiSpeed (R210.1 R211.1 R213.1 R215.1), HighSpeed/Power4HighSpeed/U_Pomiar_pradu_napiecia_PCIe4 (U64_U_Pomiar_pradu_napiecia_PCIe4.2)
NetR217_1: Power4HiSpeed (R217.1 R219.1 R221.1 R222.1), HighSpeed/Power4HighSpeed/U_Pomiar_pradu_napiecia_PCIe4 (U64_U_Pomiar_pradu_napiecia_PCIe4.1)
NetR229_1: Power_Distribution (R229.1 R230.1 R457.1 R459.1), PowerDistribition/U_Pomiar_pradu_napiecia_1 (U64_U_Pomiar_pradu_napiecia_1.2)
NetR231_SPI_bridge_Main_1: HighSpeed/SPI_bridge_PCIe (5 pins), SPI_bridge_Main (R231_SPI_bridge_Main.1 SP21_SPI_bridge_Main.1 U24_SPI_bridge_Main.11)
NetR240_SPI_bridge_Main_1: WR_Clock (R912.1), SPI_bridge_Main (R240_SPI_bridge_Main.1 SP29_SPI_bridge_Main.1 U28_SPI_bridge_Main.11)
NetR241_2: GPIO_I2C (R241.2 R242.1), Ext_GPIO/I2C_Bridge_GPIO (U3_I2C_Bridge_GPIO.22)
NetR243_2: GPIO_I2C (R243.2 R244.1), Ext_GPIO/I2C_Bridge_GPIO (U3_I2C_Bridge_GPIO.23)
NetR281_2: GPIO_I2C (R281.2 R400.1), Ext_GPIO/I2C_Bridge_GPIO (U3_I2C_Bridge_GPIO.18)
NetR304_1: Power_Hi_Curr (R304.1 R388.1 R389.1 R390.1), Pomiar_napiecia_high_curr (U72.1)
NetR449_2: JESD204_B_or_C (R449.2 R450.1), HighSpeed/I2C_Bridge_PCIE (U3_I2C_Bridge_PCIE.22)
NetR451_2: JESD204_B_or_C (R451.2 R452.1), HighSpeed/I2C_Bridge_PCIE (U3_I2C_Bridge_PCIE.23)
NetR453_2: JESD204_B_or_C (R453.2 R454.1), HighSpeed/I2C_Bridge_PCIE (U3_I2C_Bridge_PCIE.18)
NetR455_2: Power_Distribution (R455.2 R456.1), PowerDistribition/I2C_Expander_PWR_Dist (U35_I2C_Expander_PWR_Dist.13)
NetR458_2: Power_Distribution (R458.2 R460.1), PowerDistribition/I2C_Expander_PWR_Dist (U35_I2C_Expander_PWR_Dist.12)
NetR461_1: Power_Distribution (R461.1 R463.1 R465.1 R466.1), PowerDistribition/U_Pomiar_pradu_napiecia_1 (U64_U_Pomiar_pradu_napiecia_1.1)
NetR462_2: Power_Distribution (R462.2 R464.1), PowerDistribition/I2C_Expander_PWR_Dist (U35_I2C_Expander_PWR_Dist.11)
NetR467_1: Power_Distribution (R467.1 R468.1 R593.1 R594.1), PowerDistribition/U_Pomiar_pradu_napiecia_2 (U64_U_Pomiar_pradu_napiecia_2.2)
NetR469_2: SFP_Group (R469.2 R470.1), SFP_Group+IMU/I2C_Bridge_SFP (U3_I2C_Bridge_SFP.22)
NetR471_2: SFP_Group (R471.2 R472.1), SFP_Group+IMU/I2C_Bridge_SFP (U3_I2C_Bridge_SFP.23)
NetR473_2: SFP_Group (R473.2 R474.1), SFP_Group+IMU/I2C_Bridge_SFP (U3_I2C_Bridge_SFP.18)
NetR475_2: SFP_Group (R475.2 R476.1), SFP_Group+IMU/I2C_Expander_SFP (U35_I2C_Expander_SFP.13)
NetR477_2: SFP_Group (R477.2 R478.1), SFP_Group+IMU/I2C_Expander_SFP (U35_I2C_Expander_SFP.12)
NetR479_2: SFP_Group (R479.2 R480.1), SFP_Group+IMU/I2C_Expander_SFP (U35_I2C_Expander_SFP.11)
NetR481_2: DAC (R481.2), SPI_bridge_Main (U27_SPI_bridge_Main.13)
NetR561_1: Power_Hi_Curr (R561.1 R562.1 R563.1 R564.1), PowerDistribition/HiCurrent/U_Pomiar_pradu_napiecia_3 (U64_U_Pomiar_pradu_napiecia_3.2)
NetR565_1: Power_Hi_Curr (R565.1 R566.1 R567.1 R568.1), PowerDistribition/HiCurrent/U_Pomiar_pradu_napiecia_3 (U64_U_Pomiar_pradu_napiecia_3.1)
NetR569_1: Power_Hi_Curr (R569.1 R570.1 R571.1 R572.1), PowerDistribition/HiCurrent/U_Pomiar_pradu_napiecia_4 (U64_U_Pomiar_pradu_napiecia_4.2)
NetR573_1: Power_Hi_Curr (R573.1 R574.1 R575.1 R576.1), PowerDistribition/HiCurrent/U_Pomiar_pradu_napiecia_4 (U64_U_Pomiar_pradu_napiecia_4.1)
NetR577_1: Power_Hi_Curr (R577.1 R578.1 R579.1 R580.1), PowerDistribition/HiCurrent/U_Pomiar_pradu_napiecia_5 (U64_U_Pomiar_pradu_napiecia_5.2)
NetR581_1: Power_Hi_Curr (R581.1 R582.1 R583.1 R584.1), PowerDistribition/HiCurrent/U_Pomiar_pradu_napiecia_5 (U64_U_Pomiar_pradu_napiecia_5.1)
NetR585_1: Power_Hi_Curr (R585.1 R586.1 R587.1 R588.1), PowerDistribition/HiCurrent/U_Pomiar_pradu_napiecia_6 (U64_U_Pomiar_pradu_napiecia_6.2)
NetR589_1: Power_Hi_Curr (R589.1 R590.1 R591.1 R592.1), PowerDistribition/HiCurrent/U_Pomiar_pradu_napiecia_6 (U64_U_Pomiar_pradu_napiecia_6.1)
NetR595_1: Power_Distribution (R595.1 R596.1 R597.1 R598.1), PowerDistribition/U_Pomiar_pradu_napiecia_2 (U64_U_Pomiar_pradu_napiecia_2.1)
NetR738_2: Zasilanie_CLKDistribution (R738.2 R739.2), PowerDistribition/Zasilanie CLK/I2C_Expander_PWR_CLK (U35_I2C_Expander_PWR_CLK.13)
NetR740_2: Zasilanie_CLKDistribution (R740.2 R741.2), PowerDistribition/Zasilanie CLK/I2C_Expander_PWR_CLK (U35_I2C_Expander_PWR_CLK.12)
NetR742_2: Zasilanie_CLKDistribution (R742.2 R743.2), PowerDistribition/Zasilanie CLK/I2C_Expander_PWR_CLK (U35_I2C_Expander_PWR_CLK.11)
NetR749_1: Expander_RESET (R749.1), U_Expander_RESET/I2C_Expander_Main_Rst (U35_I2C_Expander_Main_Rst.20)
NetR750_1: Expander_RESET (R750.1), U_Expander_RESET/I2C_Expander_Main_Rst (U35_I2C_Expander_Main_Rst.21)
NetR751_1: Expander_RESET (R751.1), U_Expander_RESET/I2C_Expander_Main_Rst (U35_I2C_Expander_Main_Rst.22)
NetR752_1: Expander_RESET (R752.1), U_Expander_RESET/I2C_Expander_Main_Rst (U35_I2C_Expander_Main_Rst.23)
NetR753_1: Expander_RESET (R753.1), U_Expander_RESET/I2C_Expander_Main_Rst (U35_I2C_Expander_Main_Rst.25)
NetR754_1: PowerDistribition/Zasilanie CLK/I2C_Expander_PWR_CLK (U35_I2C_Expander_PWR_CLK.14), Expander_RESET (R754.1), U_Expander_RESET/I2C_Expander_Main_Rst (U35_I2C_Expander_Main_Rst.26)
NetR758_2: Expander_RESET (R758.2 R759.1), U_Expander_RESET/I2C_Expander_Main_Rst (U35_I2C_Expander_Main_Rst.13)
